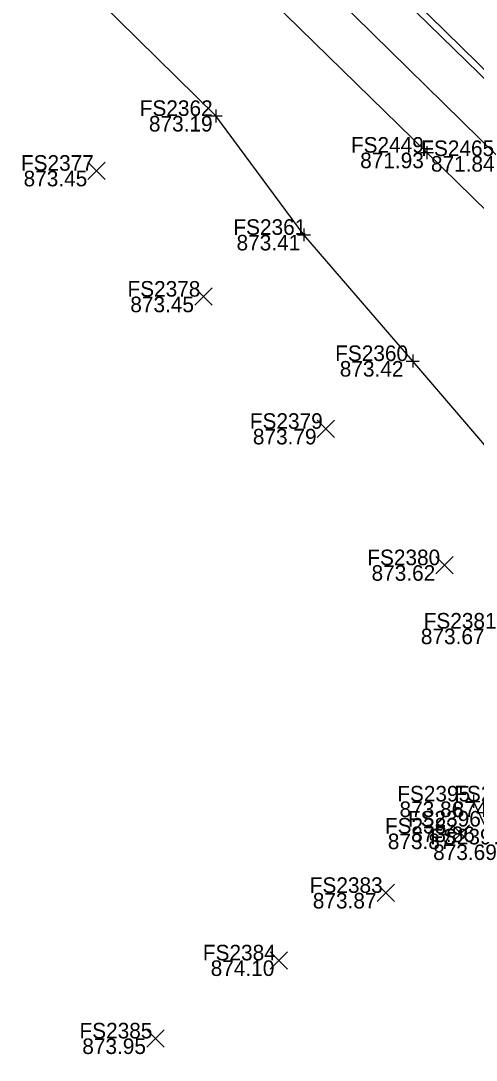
# Model space of a CAD drawing. Extents: x 1479420 to 1479833, y 379731 to 380103.
# Drawn here: x 1479498.8 to 1479533.9, y 379907.1 to 379987.2 of the extents above; entities that cross this region are included whole.
import ezdxf

# ---------------------------------------------------------------- set-up
doc = ezdxf.new("R2010")
doc.units = 0
for name, color, linetype in [('PV_X_Curb', 7, 'Continuous'), ('PV_X_Walk', 7, 'Continuous'), ('SV_X_Break_Lines', 7, 'Continuous'), ('SV_X_Random_Point', 7, 'Continuous'), ('SV_X_Shot_Marker', 7, 'Continuous'), ('SV_X_Text_Elevation', 7, 'Continuous'), ('SV_X_Text_Name', 7, 'Continuous'), ('VG_X_Flower_Bed', 7, 'Continuous')]:
    doc.layers.add(name, color=color, linetype=linetype)

msp = doc.modelspace()

# ---------------------------------------------------------------- linework, layer by layer
at = {"layer": 'PV_X_Curb'}
for points in [[(1479465.217, 380050.646), (1479478.531, 380037.631), (1479495.524, 380020.938), (1479511.459, 380005.334), (1479526.353, 379990.752), (1479540.932, 379976.569), (1479555.934, 379961.972), (1479555.892, 379961.631), (1479559.685, 379957.777), (1479564.545, 379952.777), (1479567.017, 379949.687), (1479570.003, 379944.359), (1479571.368, 379941.515), (1479571.64, 379940.628), (1479572.403, 379938.2), (1479572.729, 379936.736), (1479572.917, 379935.416), (1479573.286, 379931.116), (1479573.281, 379927.358), (1479572.586, 379922.13), (1479571.403, 379917.504), (1479569.157, 379912.511), (1479566.948, 379909.055), (1479563.851, 379905.522)], [(1479465.43, 380051.173), (1479478.923, 380037.911), (1479495.631, 380021.426), (1479511.639, 380005.785), (1479526.613, 379991.238), (1479541.434, 379976.722), (1479556.225, 379962.402), (1479558.522, 379960.088), (1479562.263, 379956.631), (1479564.944, 379953.172), (1479567.55, 379949.792), (1479570.394, 379944.783), (1479571.863, 379941.541), (1479572.44, 379940.294), (1479572.888, 379938.328), (1479573.209, 379936.746), (1479573.486, 379935.414), (1479573.818, 379931.241), (1479573.756, 379927.245), (1479573.045, 379921.888), (1479571.771, 379917.234), (1479569.497, 379912.161), (1479567.166, 379908.643), (1479563.944, 379905.002)]]:
    msp.add_lwpolyline(points, dxfattribs=at)
at = {"layer": 'PV_X_Walk'}
for points in [[(1479459.693, 380050.631), (1479472.079, 380039.157), (1479482.634, 380028.96), (1479496.943, 380014.955), (1479511.111, 380000.888), (1479521.784, 379990.322), (1479535.54, 379976.798), (1479546.783, 379965.861), (1479553.984, 379958.805), (1479560.12, 379952.427), (1479566.081, 379946.058), (1479567.842, 379944.161), (1479569.592, 379942.392), (1479571.25, 379941.414)], [(1479571.225, 379941.406), (1479571.443, 379940.74), (1479572.055, 379938.942), (1479572.399, 379937.356), (1479572.583, 379936.247), (1479572.708, 379935.62), (1479569.085, 379935.113), (1479567.56, 379937.205), (1479566.035, 379939.554), (1479564.616, 379941.63), (1479559.488, 379947.364), (1479553.278, 379954.086), (1479540.659, 379966.748), (1479530.117, 379977.06), (1479515.964, 379990.896), (1479504.534, 380001.709), (1479490.824, 380015.396), (1479476.31, 380029.289), (1479463.443, 380042.077), (1479456.834, 380048.374)]]:
    msp.add_lwpolyline(points, dxfattribs=at)
at = {"layer": 'SV_X_Break_Lines'}
msp.add_lwpolyline([(1479534.387, 379905.648), (1479543.524, 379912.475), (1479551.336, 379918.185), (1479553.597, 379921.305), (1479553.861, 379925.501), (1479552.129, 379929.668), (1479547.926, 379935.993), (1479545.155, 379941.461), (1479539.822, 379948.42), (1479529.018, 379961.007), (1479520.635, 379970.728), (1479513.841, 379979.888), (1479504.809, 379988.776), (1479495.63, 379998.694), (1479487.89, 380006.933), (1479478.402, 380016.952), (1479472.872, 380022.536)], dxfattribs=at)
at = {"layer": 'SV_X_Random_Point'}
for p, q in [((1479503.987, 379974.998), (1479505.321, 379976.333)), ((1479503.987, 379976.333), (1479505.321, 379974.998)), ((1479512.212, 379965.301), (1479513.546, 379966.636)), ((1479512.212, 379966.636), (1479513.546, 379965.301)), ((1479521.641, 379955.117), (1479522.975, 379956.452)), ((1479521.641, 379956.452), (1479522.975, 379955.117)), ((1479530.808, 379944.611), (1479532.142, 379945.946)), ((1479530.808, 379945.946), (1479532.142, 379944.611)), ((1479532.052, 379923.939), (1479533.386, 379925.274)), ((1479532.052, 379925.274), (1479533.386, 379923.939)), ((1479526.272, 379919.365), (1479527.606, 379920.7)), ((1479526.272, 379920.7), (1479527.606, 379919.365)), ((1479518.021, 379914.169), (1479519.355, 379915.504)), ((1479518.021, 379915.504), (1479519.355, 379914.169)), ((1479508.521, 379908.156), (1479509.855, 379909.491)), ((1479508.521, 379909.491), (1479509.855, 379908.156))]:
    msp.add_line(p, q, dxfattribs=at)
at = {"layer": 'SV_X_Shot_Marker'}
for p, q in [((1479513.841, 379980.388), (1479513.841, 379979.388)), ((1479513.341, 379979.888), (1479514.341, 379979.888)), ((1479513.841, 379979.888), (1479513.841, 379979.888)), ((1479529.617, 379977.06), (1479530.617, 379977.06)), ((1479530.117, 379977.56), (1479530.117, 379976.56)), ((1479530.117, 379977.06), (1479530.117, 379977.06)), ((1479520.635, 379971.228), (1479520.635, 379970.228)), ((1479520.135, 379970.728), (1479521.135, 379970.728)), ((1479520.635, 379970.728), (1479520.635, 379970.728)), ((1479528.518, 379961.007), (1479529.518, 379961.007)), ((1479529.018, 379961.507), (1479529.018, 379960.507)), ((1479529.018, 379961.007), (1479529.018, 379961.007)), ((1479533.698, 379927.579), (1479533.698, 379926.579)), ((1479533.198, 379927.079), (1479534.198, 379927.079)), ((1479533.698, 379927.079), (1479533.698, 379927.079))]:
    msp.add_line(p, q, dxfattribs=at)
at = {"layer": 'VG_X_Flower_Bed'}
msp.add_lwpolyline([(1479533.698, 379927.079), (1479534.597, 379925.146), (1479536.243, 379923.77), (1479539.845, 379923.271), (1479543.523, 379922.022), (1479545.694, 379920.151), (1479549.444, 379919.439), (1479552.948, 379924.408), (1479552.838, 379926.495), (1479549.733, 379927.527), (1479547.321, 379929.919), (1479546.286, 379933.497), (1479544.162, 379935.948), (1479540.166, 379936.781)], dxfattribs=at)

# ---------------------------------------------------------------- texts
at = {"layer": 'SV_X_Text_Elevation'}
for s, p in [('873.19', (1479508.683, 379978.688)), ('871.93', (1479524.968, 379975.86)), ('871.84', (1479530.42, 379975.598)), ('873.45', (1479499.023, 379974.466)), ('873.41', (1479515.438, 379969.528)), ('873.45', (1479507.248, 379964.768)), ('873.42', (1479523.396, 379959.807)), ('873.79', (1479516.696, 379954.584)), ('873.62', (1479525.844, 379944.079)), ('873.67', (1479529.645, 379939.196)), ('873.86', (1479528.001, 379925.879)), ('874.23', (1479532.1, 379925.883)), ('873.86', (1479528.9, 379923.946)), ('873.87', (1479527.097, 379923.406)), ('873.69', (1479530.593, 379922.57)), ('873.87', (1479521.317, 379918.833)), ('874.10', (1479513.445, 379913.636)), ('873.95', (1479503.547, 379907.624))]:
    msp.add_text(s, height=1.2, dxfattribs=at).set_placement(p)
at = {"layer": 'SV_X_Text_Name'}
for s, p in [('FS2362', (1479507.974, 379979.888)), ('FS2449', (1479524.25, 379977.06)), ('FS2465', (1479529.673, 379976.798)), ('FS2377', (1479498.815, 379975.666)), ('FS2361', (1479515.192, 379970.728)), ('FS2378', (1479507.031, 379965.968)), ('FS2360', (1479523.037, 379961.007)), ('FS2379', (1479516.46, 379955.784)), ('FS2380', (1479525.513, 379945.279)), ('FS2381', (1479529.862, 379940.396)), ('FS2395', (1479527.821, 379927.079)), ('FS2410', (1479532.214, 379927.083)), ('FS2382', (1479526.871, 379924.606)), ('FS2396', (1479528.645, 379925.146)), ('FS2397', (1479530.366, 379923.77)), ('FS2383', (1479521.081, 379920.033)), ('FS2384', (1479512.84, 379914.836)), ('FS2385', (1479503.33, 379908.824))]:
    msp.add_text(s, height=1.2, dxfattribs=at).set_placement(p)

doc.saveas('drawing.dxf')
